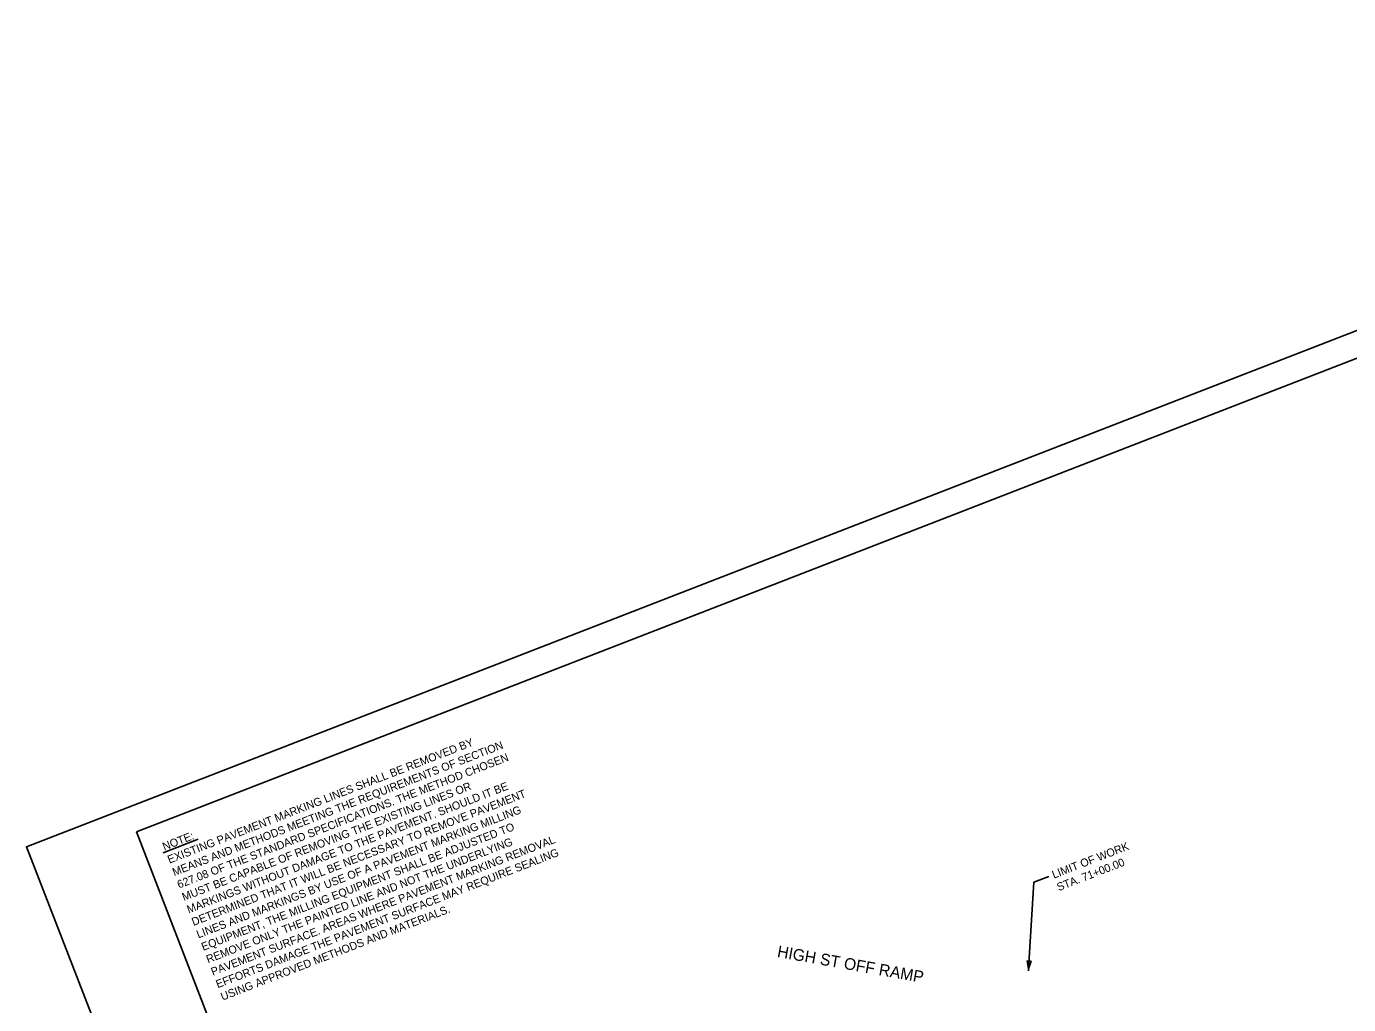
# Model space of a CAD drawing. Extents: x 1668445 to 1669436, y 339301 to 340121.
# Drawn here: x 1668444.9 to 1668940.6, y 339754.7 to 340121.3 of the extents above; entities that cross this region are included whole.
import ezdxf

# ---------------------------------------------------------------- set-up
doc = ezdxf.new("R2010")
doc.units = 0
for name, color, linetype in [('ANNOTATION', 7, 'Continuous'), ('BORDER', 7, 'Continuous'), ('PATTERNING', 7, 'Continuous'), ('PLOT BOUNDARY', 7, 'Continuous')]:
    doc.layers.add(name, color=color, linetype=linetype)

msp = doc.modelspace()

# ---------------------------------------------------------------- linework, layer by layer
at = {"layer": 'ANNOTATION'}
for p, q in [((1668496.19, 339811.53), (1668509.33, 339816.62)), ((1668820.66, 339768.02), (1668822.58, 339800.52)), ((1668828.18, 339802.69), (1668822.58, 339800.52))]:
    msp.add_line(p, q, dxfattribs=at)
msp.add_lwpolyline([(1668821.58, 339770.97), (1668820.66, 339768.02), (1668820.09, 339771.06)], close=True, dxfattribs=at)
at = {"layer": 'BORDER'}
for p, q in [((1669232.02, 340108.76), (1668486.16, 339819.44)), ((1668486.16, 339819.44), (1668676.03, 339329.98))]:
    msp.add_line(p, q, dxfattribs=at)
at = {"layer": 'PATTERNING'}
msp.add_line((1668820.61, 339767.27), (1668820.75, 339769.27), dxfattribs=at)
at = {"layer": 'PLOT BOUNDARY'}
msp.add_lwpolyline([(1668643.83, 339301.08), (1669436.3, 339608.48), (1669237.39, 340121.26), (1668444.93, 339813.86)], close=True, dxfattribs=at)

# ---------------------------------------------------------------- texts
at = {"layer": 'ANNOTATION'}
for s, height, rotation, p in [('EXISTING PAVEMENT MARKING LINES SHALL BE REMOVED BY ', 3, 21.2013, (1668498.51, 339807.49)), ('MEANS AND METHODS MEETING THE REQUIREMENTS OF SECTION ', 3, 21.2013, (1668500.33, 339802.81)), ('627.08 OF THE STANDARD SPECIFICATIONS. THE METHOD CHOSEN ', 3, 21.2013, (1668502.14, 339798.14)), ('MUST BE CAPABLE OF REMOVING THE EXISTING LINES OR ', 3, 21.2013, (1668503.95, 339793.47)), ('MARKINGS WITHOUT DAMAGE TO THE PAVEMENT. SHOULD IT BE ', 3, 21.2013, (1668505.76, 339788.8)), ('DETERMINED THAT IT WILL BE NECESSARY TO REMOVE PAVEMENT ', 3, 21.2013, (1668507.57, 339784.13)), ('LINES AND MARKINGS BY USE OF A PAVEMENT MARKING MILLING ', 3, 21.2013, (1668509.38, 339779.46)), ('NOTE:', 3, 21.2013, (1668496.62, 339812.37)), ('EQUIPMENT, THE MILLING EQUIPMENT SHALL BE ADJUSTED TO ', 3, 21.2013, (1668511.2, 339774.79)), ('REMOVE ONLY THE PAINTED LINE AND NOT THE UNDERLYING ', 3, 21.2013, (1668513.01, 339770.12)), ('PAVEMENT SURFACE. AREAS WHERE PAVEMENT MARKING REMOVAL ', 3, 21.2013, (1668514.82, 339765.45)), ('LIMIT OF WORK', 3, 21.2013, (1668830.12, 339801.84)), ('EFFORTS DAMAGE THE PAVEMENT SURFACE MAY REQUIRE SEALING ', 3, 21.2013, (1668516.63, 339760.78)), ('STA. 71+00.00', 3, 21.2013, (1668831.93, 339797.16)), ('USING APPROVED METHODS AND MATERIALS.', 3, 21.2013, (1668518.44, 339756.11)), ('HIGH ST OFF RAMP', 4.375, 349.8993, (1668726.18, 339772.56))]:
    msp.add_text(s, height=height, rotation=rotation, dxfattribs=at).set_placement(p)

doc.saveas('drawing.dxf')
